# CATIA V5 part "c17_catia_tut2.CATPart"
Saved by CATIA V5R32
Part number: Part1
Bounding box of the stored display mesh (mm): x -65 to 65, y -120 to 120, z -37.621 to 37.5
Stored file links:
  D:\PROJECTS\Project 2022\CATIA V5 6R 2022\Resources\Tutorial Files\c17_catia_v5_6r2022_tut\c17_catia_tut2.CATPart
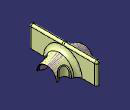
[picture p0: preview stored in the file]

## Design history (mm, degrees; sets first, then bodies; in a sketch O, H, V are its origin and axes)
Body1 (main body)
  Sketch1 on zx-plane, origin (0, 0, 0), H (-1, 0, 0), V (0, 0, 1)
    line L1 (7.5, 37.5) -> (7.5, -37.5)
    line L2 (-7.5, -37.5) -> (-7.5, 37.5)
    line L3 (-7.5, 37.5) -> (7.5, 37.5)
    point P2 (7.5, -37.5)
    distance L1 L2 = 15
    length L1 = 75
    distance H P2 = 37.5
    vertical: L1 V, L2 V
    horizontal: L3 H
    equidistance: L1 L2 O
  Extrude1: Element1 Sketch1, Lim1 120, Lim2 120
  Sketch2 on face of Extrude1 from Sketch1.L2, origin (7.5, 0, 0), H (0, -1, 0), V (0, 0, 1)
    arc A1 centre (0, -37.6505) radius 55 from (55, -37.6505) to (-55, -37.6505) ccw
    point P1 (0, -37.6505)
    axis line L1 (-118.7489, -37.6505) -> (99.6231, -37.6505)
    point P4 (-55, -37.6505)
    point P5 (55, -37.6505)
    radius A1 = 55
    coincidence: P1 V, L1 P4, L1 P5
    horizontal: L1 H
  Plane1: type Offset, RefPlane yz-plane, Offset 65
  Sketch3 on Plane1, origin (65, 0, 0), H (0, 1, 0), V (0, 0, 1)
    arc A1 centre (0, -37.9724) radius 35 from (34.9968, -37.5) to (-34.9968, -37.5) ccw
    point P1 (0, -37.9724)
    axis line L1 (106.4819, -37.5) -> (-95.6002, -37.5)
    reference projected line E1 (-120, -37.5) -> (120, -37.5) from edge of Extrude1
    point P4 (-34.9968, -37.5)
    point P5 (34.9968, -37.5)
    radius A1 = 35
    coincidence: P1 V, L1 E1, L1 P4, L1 P5
    horizontal: L1 H
  Loft1: Sections (Sketch3; Sketch2)
  Symmetry1: ToTransfor Loft1, Reference yz-plane
  Line1: type PtPt, FirstPoint vertex [face of Extrude1 from Sketch1.L2], SecondPoint vertex [face of Extrude1 from Sketch1.L1]
  Fill1: Boundary (edge of Extrude1; edge of Extrude1; edge of Extrude1; Line1)
  Line2: type PtPt, FirstPoint vertex [face of Extrude1 from Sketch1.L1], SecondPoint vertex [face of Extrude1 from Sketch1.L2]
  Fill2: Boundary (edge of Extrude1; edge of Extrude1; edge of Extrude1; Line2)
  Trim1: Trimmed (Loft1; Extrude1)
  Trim2: Trimmed (Symmetry1; Trim1)
  Join1: Elements (Fill1; Trim2; Fill2)
  Sketch4 on xy-plane, origin (0, 0, 0), H (1, 0, 0), V (0, 1, 0)
    circle A1 centre (43, 42) radius 15
    point P1 (43, 42)
    circle A2 centre (43, -42) radius 15
    distance P1 H = 42
    radius A1 = 15
    symmetry: A1 A2 H
  Extrude2: Element1 Sketch4, Lim1 40, Lim2 0, FirstUpto vertex [face of Loft1]
  Trim3: Trimmed (Extrude2; Join1)
  Fillet1: radius 18, on edge [face of Extrude1 from Sketch1.L2 | face of Loft1]; edge [face of Symmetry1 | face of Extrude1 from Sketch1.L1]
  Fillet2: radius 4, on edge [face of Loft1 | face of Extrude2 from Sketch4.A1]
  Fillet3: radius 7.5, on edge [face of Fill1 | face of Extrude1 from Sketch1.L3]; edge [face of Extrude1 from Sketch1.L3 | face of Fill2]; edge [face of Extrude1 from Sketch1.L2 | face of Extrude1 from Sketch1.L3]; edge [face of Extrude1 from Sketch1.L3 | face of Extrude1 from Sketch1.L1]; edge [face of Extrude1 from Sketch1.L2 | face of Fill2]; edge [face of Fill1 | face of Extrude1 from Sketch1.L2]; edge [face of Fill1 | face of Extrude1 from Sketch1.L1]; edge [face of Extrude1 from Sketch1.L1 | face of Fill2]
  Fillet4: radius 4, on edge [face of Extrude2 from Sketch4.A2 | face of Loft1]
  Set1
    ThickSurface1: BotOffset 0, Surface Fillet4, TopOffset 1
